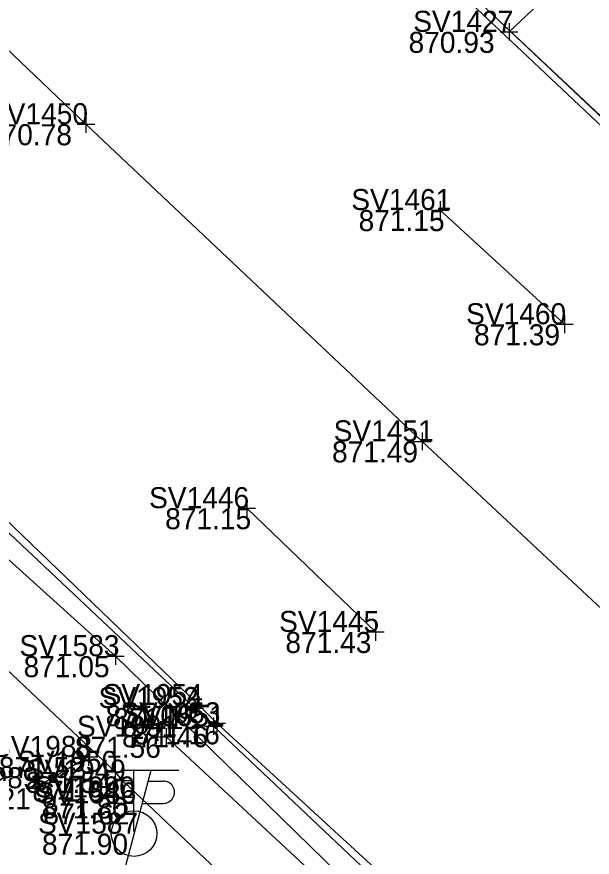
# Model space of a CAD drawing. Extents: x 1480001 to 1480402, y 379235 to 379603.
# Drawn here: x 1480045.05 to 1480077.88, y 379498.74 to 379546.67 of the extents above; entities that cross this region are included whole.
import ezdxf

# ---------------------------------------------------------------- set-up
doc = ezdxf.new("R2010")
doc.units = 0
for name, color, linetype in [('PM_P_CL_Double_Solid', 7, 'Continuous'), ('PM_X_Lane_Line', 7, 'Continuous'), ('PV_X_Curb', 7, 'Continuous'), ('PV_X_Driveway', 7, 'Continuous'), ('PV_X_Walk', 7, 'Continuous'), ('SN_X_Public', 7, 'Continuous'), ('SV_X_Shot_Marker', 7, 'Continuous'), ('SV_X_Text_Elevation', 7, 'Continuous'), ('SV_X_Text_Name', 7, 'Continuous'), ('UT_X_Misc_Cells', 7, 'Continuous'), ('UT_X_Water', 7, 'Continuous')]:
    doc.layers.add(name, color=color, linetype=linetype)

msp = doc.modelspace()

# ---------------------------------------------------------------- linework, layer by layer
at = {"layer": 'PM_P_CL_Double_Solid'}
msp.add_lwpolyline([(1480030.312, 379558.368), (1480048.994, 379540.544), (1480068.184, 379522.458), (1480086.697, 379505.162), (1480104.247, 379488.61), (1480122.276, 379471.896), (1480139.96, 379455.601)], dxfattribs=at)
at = {"layer": 'PM_X_Lane_Line'}
for p, q in [((1480076.297, 379529.135), (1480069.209, 379535.648)), ((1480065.512, 379511.587), (1480058.171, 379518.646))]:
    msp.add_line(p, q, dxfattribs=at)
at = {"layer": 'PV_X_Curb'}
for points in [[(1480043.308, 379574.086), (1480051.435, 379566.534), (1480067.64, 379551.083), (1480087.827, 379532.141), (1480105.189, 379515.816), (1480105.937, 379515.205), (1480115.287, 379506.588), (1480116.588, 379505.377), (1480116.999, 379505.563), (1480121.373, 379501.34), (1480121.053, 379501.135), (1480146.64, 379476.909), (1480171.177, 379454.102), (1480173.021, 379452.229), (1480182.175, 379443.675), (1480183.379, 379442.683), (1480186.184, 379440.013), (1480186.975, 379439.363), (1480207.407, 379420.301)], [(1480042.95, 379573.802), (1480051.182, 379566.018), (1480067.383, 379550.834), (1480087.586, 379531.809), (1480105.067, 379515.41), (1480105.589, 379514.887), (1480115.079, 379506.297), (1480116.303, 379505.052), (1480118.53, 379502.967), (1480120.902, 379500.821), (1480138.714, 379483.703), (1480170.84, 379453.681), (1480172.574, 379452.083), (1480181.867, 379443.345), (1480182.839, 379442.217), (1480185.607, 379439.661), (1480186.493, 379438.955), (1480206.919, 379419.855)], [(1480135.19, 379432.332), (1480118.45, 379448.16), (1480110.152, 379455.954), (1480109.273, 379456.61), (1480100.92, 379464.722), (1480096.044, 379469.27), (1480093.779, 379471.437), (1480091.422, 379473.761), (1480089.145, 379475.876), (1480069.411, 379494.504), (1480056.455, 379506.379), (1480055.435, 379507.417), (1480042.302, 379520.019), (1480041.64, 379520.833), (1480030.984, 379530.729), (1480016.059, 379544.67)], [(1480135, 379431.897), (1480118.039, 379447.914), (1480109.91, 379455.647), (1480108.98, 379456.443), (1480100.472, 379464.439), (1480095.645, 379469.163), (1480093.387, 379471.311), (1480093.127, 379470.939), (1480088.623, 379475.041), (1480088.838, 379475.368), (1480068.906, 379494.276), (1480056.264, 379506.212), (1480055.202, 379507.245), (1480042.335, 379519.353), (1480041.39, 379520.138), (1480030.539, 379530.321), (1480016.21, 379543.914)]]:
    msp.add_lwpolyline(points, dxfattribs=at)
at = {"layer": 'PV_X_Driveway'}
msp.add_line((1480049.143, 379504.46), (1480046.074, 379502.673), dxfattribs=at)
msp.add_lwpolyline([(1480073.139, 379545.812), (1480077.692, 379550.115), (1480090.058, 379539.2), (1480093.891, 379543.58)], dxfattribs=at)
at = {"layer": 'PV_X_Walk'}
for points in [[(1480132.903, 379425.968), (1480114.834, 379442.96), (1480103.251, 379453.811), (1480091.01, 379465.628), (1480083.545, 379472.507), (1480065.123, 379489.824), (1480051.079, 379503.111), (1480050.67, 379503.609), (1480040.657, 379513.03), (1480041.273, 379513.837), (1480027.417, 379527.179), (1480013.329, 379540.204)], [(1480053.564, 379505.61), (1480071.797, 379488.664), (1480089.369, 379472.273), (1480095.978, 379465.936)]]:
    msp.add_lwpolyline(points, dxfattribs=at)
at = {"layer": 'SN_X_Public'}
for p, q in [((1480051.7, 379503.749), (1480051.7, 379500.549)), ((1480051.707, 379503.409), (1480051.707, 379500.209)), ((1480051.7, 379502.149), (1480050.1, 379502.149)), ((1480051.707, 379501.809), (1480050.107, 379501.809))]:
    msp.add_line(p, q, dxfattribs=at)
at = {"layer": 'SV_X_Shot_Marker'}
for p, q in [((1480073.139, 379546.312), (1480073.139, 379545.312)), ((1480072.639, 379545.812), (1480073.639, 379545.812)), ((1480073.139, 379545.812), (1480073.139, 379545.812)), ((1480048.994, 379541.044), (1480048.994, 379540.044)), ((1480048.494, 379540.544), (1480049.494, 379540.544)), ((1480048.994, 379540.544), (1480048.994, 379540.544)), ((1480069.209, 379536.148), (1480069.209, 379535.148)), ((1480068.709, 379535.648), (1480069.709, 379535.648)), ((1480069.209, 379535.648), (1480069.209, 379535.648)), ((1480076.297, 379529.635), (1480076.297, 379528.635)), ((1480075.797, 379529.135), (1480076.797, 379529.135)), ((1480076.297, 379529.135), (1480076.297, 379529.135)), ((1480068.184, 379522.958), (1480068.184, 379521.958)), ((1480067.684, 379522.458), (1480068.684, 379522.458)), ((1480068.184, 379522.458), (1480068.184, 379522.458)), ((1480058.171, 379519.146), (1480058.171, 379518.146)), ((1480057.671, 379518.646), (1480058.671, 379518.646)), ((1480058.171, 379518.646), (1480058.171, 379518.646)), ((1480065.512, 379512.087), (1480065.512, 379511.087)), ((1480065.012, 379511.587), (1480066.012, 379511.587)), ((1480065.512, 379511.587), (1480065.512, 379511.587)), ((1480050.678, 379510.707), (1480050.678, 379509.707)), ((1480050.178, 379510.207), (1480051.178, 379510.207)), ((1480050.678, 379510.207), (1480050.678, 379510.207)), ((1480055.435, 379507.917), (1480055.435, 379506.917)), ((1480054.935, 379507.417), (1480055.935, 379507.417)), ((1480055.202, 379507.745), (1480055.202, 379506.745)), ((1480055.435, 379507.417), (1480055.435, 379507.417)), ((1480054.702, 379507.245), (1480055.702, 379507.245)), ((1480055.202, 379507.245), (1480055.202, 379507.245)), ((1480056.264, 379506.712), (1480056.264, 379505.712)), ((1480056.455, 379506.879), (1480056.455, 379505.879)), ((1480053.564, 379506.11), (1480053.564, 379505.11)), ((1480055.764, 379506.212), (1480056.764, 379506.212)), ((1480055.955, 379506.379), (1480056.955, 379506.379)), ((1480056.264, 379506.212), (1480056.264, 379506.212)), ((1480056.455, 379506.379), (1480056.455, 379506.379)), ((1480053.064, 379505.61), (1480054.064, 379505.61)), ((1480053.564, 379505.61), (1480053.564, 379505.61)), ((1480049.143, 379504.96), (1480049.143, 379503.96)), ((1480048.643, 379504.46), (1480049.643, 379504.46)), ((1480049.143, 379504.46), (1480049.143, 379504.46)), ((1480050.67, 379504.109), (1480050.67, 379503.109)), ((1480050.17, 379503.609), (1480051.17, 379503.609)), ((1480050.67, 379503.609), (1480050.67, 379503.609)), ((1480051.079, 379503.611), (1480051.079, 379502.611)), ((1480046.074, 379503.173), (1480046.074, 379502.173)), ((1480050.579, 379503.111), (1480051.579, 379503.111)), ((1480051.079, 379503.111), (1480051.079, 379503.111)), ((1480045.574, 379502.673), (1480046.574, 379502.673)), ((1480046.074, 379502.673), (1480046.074, 379502.673))]:
    msp.add_line(p, q, dxfattribs=at)
at = {"layer": 'UT_X_Misc_Cells'}
for p, q in [((1480052.702, 379503.686), (1480051.096, 379497.686)), ((1480054.302, 379503.686), (1480051.102, 379503.686)), ((1480052.542, 379503.086), (1480053.392, 379503.086)), ((1480052.201, 379501.811), (1480053.392, 379501.811))]:
    msp.add_line(p, q, dxfattribs=at)
msp.add_circle((1480051.739, 379500.086), 1.3, dxfattribs=at)
msp.add_arc((1480053.405, 379502.449), 0.638, 268.8767, 91.1233, dxfattribs=at)
at = {"layer": 'UT_X_Water'}
for points in [[(1480049.152, 379568.017), (1480068.611, 379550.193), (1480086.403, 379533.424), (1480090.024, 379530.079), (1480102.295, 379519.134), (1480111.734, 379511.473), (1480120.332, 379509.136), (1480127.535, 379501.668), (1480127.911, 379496.395), (1480140.166, 379484.084), (1480149.088, 379474.708), (1480164.726, 379459.482), (1480172.622, 379452.503), (1480197.813, 379429.111), (1480212.628, 379415.684), (1480231.592, 379398.237)], [(1480225.088, 379345.601), (1480208.322, 379361.342), (1480207.346, 379362.25), (1480199.528, 379369.768), (1480193.21, 379375.651), (1480182.823, 379385.139), (1480177.927, 379389.525), (1480169.423, 379398.321), (1480161.035, 379406.189), (1480144.924, 379421.019), (1480134.739, 379430.559), (1480121.485, 379441.998), (1480113.085, 379450.369), (1480106.418, 379456.915), (1480094.539, 379467.985), (1480089.15, 379472.551), (1480086.751, 379474.713), (1480073.459, 379487.337), (1480068.123, 379493.187), (1480050.678, 379510.207), (1480044.404, 379515.873)]]:
    msp.add_lwpolyline(points, dxfattribs=at)

# ---------------------------------------------------------------- texts
at = {"layer": 'SV_X_Text_Elevation'}
for s, p in [('870.93', (1480067.404, 379544.612)), ('870.78', (1480043.287, 379539.344)), ('871.15', (1480064.552, 379534.448)), ('871.39', (1480071.139, 379527.935)), ('871.49', (1480063.035, 379521.258)), ('871.15', (1480053.514, 379517.446)), ('871.43', (1480060.373, 379510.387)), ('871.05', (1480045.435, 379509.007)), ('871.06', (1480050.116, 379506.217)), ('871.13', (1480050.545, 379506.045)), ('871.46', (1480051.049, 379505.012)), ('871.16', (1480051.723, 379505.179)), ('871.56', (1480048.359, 379504.41)), ('871.52', (1480044.023, 379503.26)), ('871.54', (1480045.55, 379502.409)), ('871.64', (1480045.94, 379501.911)), ('872.21', (1480040.943, 379501.473)), ('871.80', (1480046.466, 379500.949)), ('871.62', (1480046.568, 379500.609)), ('871.90', (1480046.486, 379498.886))]:
    msp.add_text(s, height=1.2, dxfattribs=at).set_placement(p)
at = {"layer": 'SV_X_Text_Name'}
for s, p in [('SV1427', (1480067.669, 379545.812)), ('SV1450', (1480043.401, 379540.544)), ('SV1461', (1480064.135, 379535.648)), ('SV1460', (1480070.685, 379529.135)), ('SV1451', (1480063.129, 379522.458)), ('SV1446', (1480052.597, 379518.646)), ('SV1445', (1480060.014, 379511.587)), ('SV1583', (1480045.199, 379510.207)), ('SV1952', (1480049.713, 379507.245)), ('SV1954', (1480049.946, 379507.417)), ('SV1953', (1480050.957, 379506.379)), ('SV1951', (1480051.2, 379506.212)), ('SV1991', (1480048.481, 379505.61)), ('SV1988', (1480043.635, 379504.46)), ('SV1950', (1480045.068, 379503.609)), ('SV1949', (1480045.562, 379503.111)), ('SV1989', (1480040.566, 379502.673)), ('SV1990', (1480046.079, 379502.149)), ('SV1586', (1480046.152, 379501.809)), ('SV1587', (1480046.26, 379500.086))]:
    msp.add_text(s, height=1.2, dxfattribs=at).set_placement(p)

doc.saveas('drawing.dxf')
